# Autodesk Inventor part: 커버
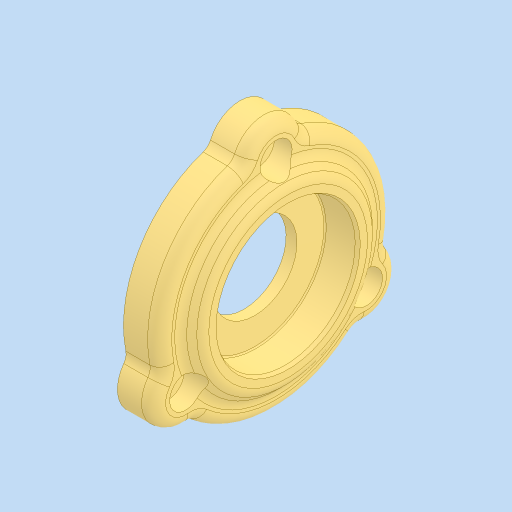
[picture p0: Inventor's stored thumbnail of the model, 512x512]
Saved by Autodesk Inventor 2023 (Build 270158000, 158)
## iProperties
Created: 2026-03
Part Number: 커버
Material: 알루미늄 6061
Document SubType Name: Modeling
Designer: home
Density: 2.7 g/cm^3
Appearance: 기본값
Author: jhkim
Sending System: Autodesk Inventor 2026
Preprocessor: ST-DEVELOPER v20.1
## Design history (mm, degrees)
feature "솔리드1"
node "솔리드2"
